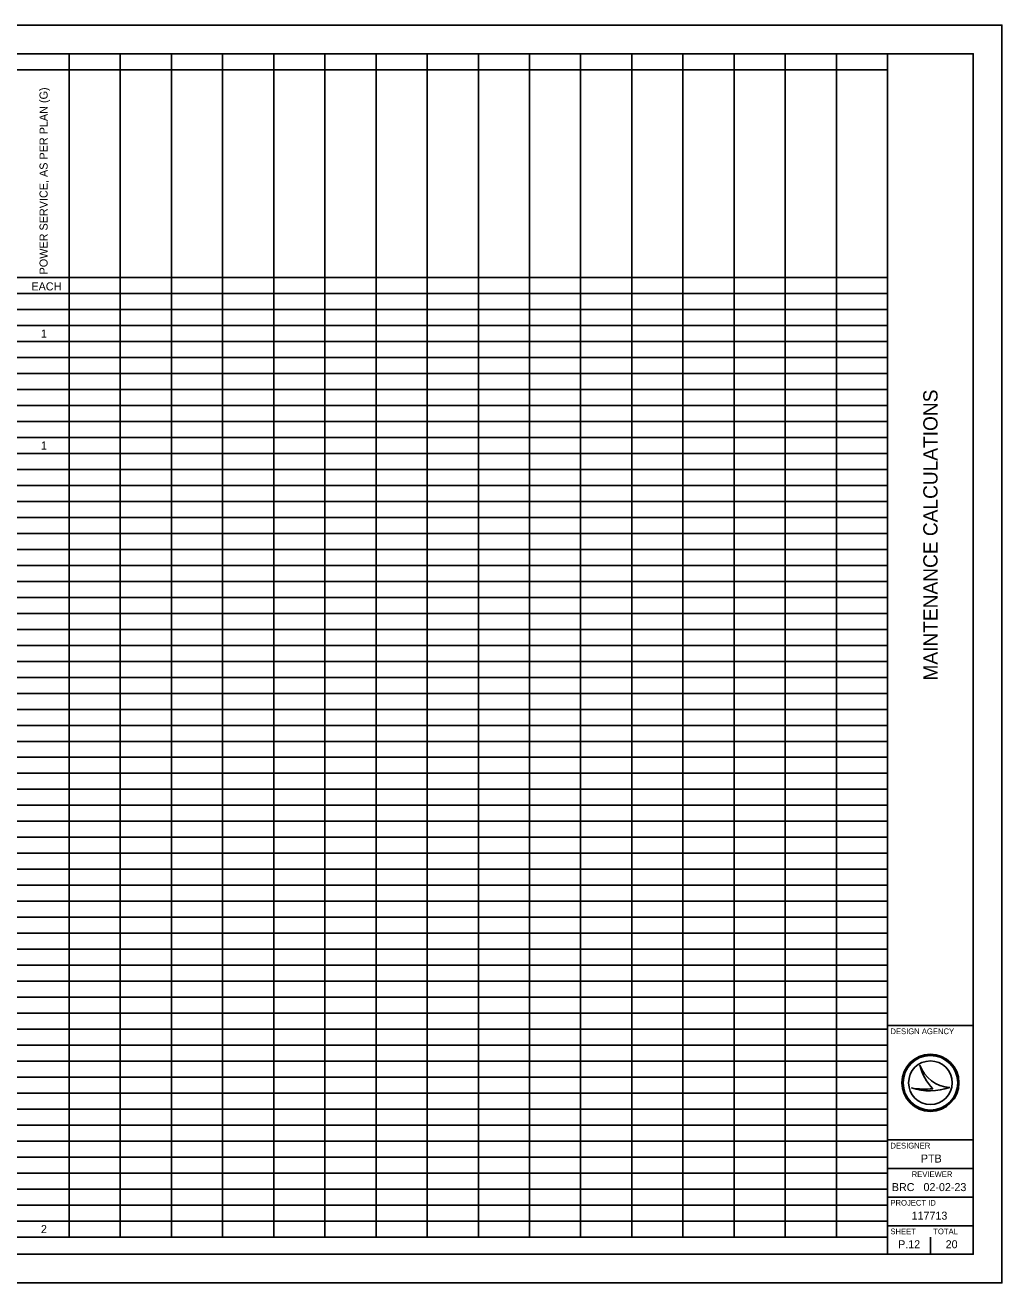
# Model space of a CAD drawing. Extents: x 0 to 34, y 0 to 22.
# Drawn here: x 16.91 to 34, y 0 to 22 of the extents above; entities that cross this region are included whole.
import ezdxf

# ---------------------------------------------------------------- set-up
doc = ezdxf.new("R2010")
doc.units = 0
for name, color, linetype in [('Default', 7, 'Continuous'), ('SH_Border', 7, 'Continuous'), ('SH_Cut_Line', 7, 'Continuous'), ('SH_Data', 7, 'Continuous')]:
    doc.layers.add(name, color=color, linetype=linetype)

msp = doc.modelspace()

# ---------------------------------------------------------------- linework, layer by layer
at = {"layer": 'Default'}
for p, q in [((7.833, 21.5), (21.259, 21.5)), ((17.679, 21.5), (17.679, 0.801)), ((18.574, 21.5), (18.574, 0.801)), ((19.469, 21.5), (19.469, 0.801)), ((20.364, 21.5), (20.364, 0.801)), ((21.259, 21.5), (32, 21.5)), ((21.259, 21.5), (21.259, 0.801)), ((22.154, 21.5), (22.154, 0.801)), ((23.049, 21.5), (23.049, 0.801)), ((23.944, 21.5), (23.944, 0.801)), ((24.839, 21.5), (24.839, 0.801)), ((25.734, 21.5), (25.734, 0.801)), ((26.629, 21.5), (26.629, 0.801)), ((27.525, 21.5), (27.525, 0.801)), ((28.42, 21.5), (28.42, 0.801)), ((29.315, 21.5), (29.315, 0.801)), ((30.21, 21.5), (30.21, 0.801)), ((31.105, 21.5), (31.105, 0.801)), ((32, 21.5), (32, 0.801)), ((8.728, 21.22), (21.259, 21.22)), ((21.259, 21.22), (32, 21.22)), ((8.728, 17.584), (21.259, 17.584)), ((21.259, 17.584), (32, 17.584)), ((7.833, 17.304), (21.259, 17.304)), ((21.259, 17.304), (32, 17.304)), ((7.833, 17.025), (21.259, 17.025)), ((21.259, 17.025), (32, 17.025)), ((7.833, 16.745), (21.259, 16.745)), ((21.259, 16.745), (32, 16.745)), ((7.833, 16.465), (21.259, 16.465)), ((21.259, 16.465), (32, 16.465)), ((7.833, 16.185), (21.259, 16.185)), ((21.259, 16.185), (32, 16.185)), ((7.833, 15.906), (21.259, 15.906)), ((21.259, 15.906), (32, 15.906)), ((7.833, 15.626), (21.259, 15.626)), ((21.259, 15.626), (32, 15.626)), ((7.833, 15.346), (21.259, 15.346)), ((21.259, 15.346), (32, 15.346)), ((7.833, 15.067), (21.259, 15.067)), ((21.259, 15.067), (32, 15.067)), ((7.833, 14.787), (21.259, 14.787)), ((21.259, 14.787), (32, 14.787)), ((7.833, 14.507), (21.259, 14.507)), ((21.259, 14.507), (32, 14.507)), ((7.833, 14.227), (21.259, 14.227)), ((21.259, 14.227), (32, 14.227)), ((7.833, 13.948), (21.259, 13.948)), ((21.259, 13.948), (32, 13.948)), ((7.833, 13.668), (21.259, 13.668)), ((21.259, 13.668), (32, 13.668)), ((7.833, 13.388), (21.259, 13.388)), ((21.259, 13.388), (32, 13.388)), ((7.833, 13.109), (21.259, 13.109)), ((21.259, 13.109), (32, 13.109)), ((7.833, 12.829), (21.259, 12.829)), ((21.259, 12.829), (32, 12.829)), ((7.833, 12.549), (21.259, 12.549)), ((21.259, 12.549), (32, 12.549)), ((7.833, 12.269), (21.259, 12.269)), ((21.259, 12.269), (32, 12.269)), ((7.833, 11.99), (21.259, 11.99)), ((21.259, 11.99), (32, 11.99)), ((7.833, 11.71), (21.259, 11.71)), ((21.259, 11.71), (32, 11.71)), ((7.833, 11.43), (21.259, 11.43)), ((21.259, 11.43), (32, 11.43)), ((7.833, 11.151), (21.259, 11.151)), ((21.259, 11.151), (32, 11.151)), ((7.833, 10.871), (21.259, 10.871)), ((21.259, 10.871), (32, 10.871)), ((7.833, 10.591), (21.259, 10.591)), ((21.259, 10.591), (32, 10.591)), ((7.833, 10.311), (21.259, 10.311)), ((21.259, 10.311), (32, 10.311)), ((7.833, 10.032), (21.259, 10.032)), ((21.259, 10.032), (32, 10.032)), ((7.833, 9.752), (21.259, 9.752)), ((21.259, 9.752), (32, 9.752)), ((7.833, 9.472), (21.259, 9.472)), ((21.259, 9.472), (32, 9.472)), ((7.833, 9.193), (21.259, 9.193)), ((21.259, 9.193), (32, 9.193)), ((7.833, 8.913), (21.259, 8.913)), ((21.259, 8.913), (32, 8.913)), ((7.833, 8.633), (21.259, 8.633)), ((21.259, 8.633), (32, 8.633)), ((7.833, 8.353), (21.259, 8.353)), ((21.259, 8.353), (32, 8.353)), ((7.833, 8.074), (21.259, 8.074)), ((21.259, 8.074), (32, 8.074)), ((7.833, 7.794), (21.259, 7.794)), ((21.259, 7.794), (32, 7.794)), ((7.833, 7.514), (21.259, 7.514)), ((21.259, 7.514), (32, 7.514)), ((7.833, 7.235), (21.259, 7.235)), ((21.259, 7.235), (32, 7.235)), ((7.833, 6.955), (21.259, 6.955)), ((21.259, 6.955), (32, 6.955)), ((7.833, 6.675), (21.259, 6.675)), ((21.259, 6.675), (32, 6.675)), ((7.833, 6.395), (21.259, 6.395)), ((21.259, 6.395), (32, 6.395)), ((7.833, 6.116), (21.259, 6.116)), ((21.259, 6.116), (32, 6.116)), ((7.833, 5.836), (21.259, 5.836)), ((21.259, 5.836), (32, 5.836)), ((7.833, 5.556), (21.259, 5.556)), ((21.259, 5.556), (32, 5.556)), ((7.833, 5.277), (21.259, 5.277)), ((21.259, 5.277), (32, 5.277)), ((7.833, 4.997), (21.259, 4.997)), ((21.259, 4.997), (32, 4.997)), ((7.833, 4.717), (21.259, 4.717)), ((21.259, 4.717), (32, 4.717)), ((7.833, 4.437), (21.259, 4.437)), ((21.259, 4.437), (32, 4.437)), ((7.833, 4.158), (21.259, 4.158)), ((21.259, 4.158), (32, 4.158)), ((7.833, 3.878), (21.259, 3.878)), ((21.259, 3.878), (32, 3.878)), ((7.833, 3.598), (21.259, 3.598)), ((21.259, 3.598), (32, 3.598)), ((7.833, 3.319), (21.259, 3.319)), ((21.259, 3.319), (32, 3.319)), ((7.833, 3.039), (21.259, 3.039)), ((21.259, 3.039), (32, 3.039)), ((7.833, 2.759), (21.259, 2.759)), ((21.259, 2.759), (32, 2.759)), ((7.833, 2.479), (21.259, 2.479)), ((21.259, 2.479), (32, 2.479)), ((7.833, 2.2), (21.259, 2.2)), ((21.259, 2.2), (32, 2.2)), ((7.833, 1.92), (21.259, 1.92)), ((21.259, 1.92), (32, 1.92)), ((7.833, 1.64), (21.259, 1.64)), ((21.259, 1.64), (32, 1.64)), ((7.833, 1.361), (21.259, 1.361)), ((21.259, 1.361), (32, 1.361)), ((7.833, 1.081), (21.259, 1.081)), ((21.259, 1.081), (32, 1.081)), ((7.833, 0.801), (21.259, 0.801)), ((21.259, 0.801), (32, 0.801))]:
    msp.add_line(p, q, dxfattribs=at)
at = {"layer": 'SH_Border'}
for p, q in [((32, 0.5), (32, 21.5)), ((32, 4.5), (33.5, 4.5)), ((32, 2.5), (33.5, 2.5)), ((32, 2), (33.5, 2)), ((32, 1.5), (33.5, 1.5)), ((32, 1), (33.5, 1))]:
    msp.add_line(p, q, dxfattribs=at)
msp.add_lwpolyline([(1.5, 21.5), (33.5, 21.5), (33.5, 0.5), (1.5, 0.5)], close=True, dxfattribs=at)
at = {"layer": 'SH_Cut_Line'}
msp.add_lwpolyline([(0, 0), (34, 0), (34, 22), (0, 22)], close=True, dxfattribs=at)
at = {"layer": 'SH_Data'}
for p, q in [((32.567, 3.81), (32.567, 3.81)), ((32.417, 3.41), (32.417, 3.41)), ((32.75, 3.5), (32.75, 3.5)), ((33.087, 3.419), (33.087, 3.419)), ((32.375, 0.675), (32.375, 0.675)), ((32.75, 0.5), (32.75, 0.8))]:
    msp.add_line(p, q, dxfattribs=at)
for radius in [0.5, 0.477, 0.477, 0.382]:
    msp.add_circle((32.75, 3.5), radius, dxfattribs=at)
for centre, radius, start, end in [((33.116, 3.998), 0.58, 198.9257, 198.9319), ((33.347, 3.97), 0.796, 191.6379, 191.6421), ((33.116, 3.998), 0.58, 198.9319, 267.1657), ((33.347, 3.97), 0.796, 191.6421, 226.0947), ((32.739, 4.37), 1.013, 251.4576, 290.0832), ((32.648, 4.654), 1.266, 259.4964, 259.4995), ((32.739, 4.37), 1.013, 251.4527, 251.4576), ((32.648, 4.654), 1.266, 259.4995, 276.6672)]:
    msp.add_arc(centre, radius, start, end, dxfattribs=at)

# ---------------------------------------------------------------- texts
at = {"layer": 'Default'}
msp.add_text('POWER SERVICE, AS PER PLAN (G)', height=0.14154, rotation=90, dxfattribs=at).set_placement((17.302, 17.64))
for s, height, p in [('EACH', 0.1415, (17.018, 17.36)), ('1', 0.142, (17.186, 16.534)), ('1', 0.142, (17.186, 14.576)), ('2', 0.142, (17.184, 0.87))]:
    msp.add_text(s, height=height, dxfattribs=at).set_placement(p)
at = {"layer": 'SH_Data'}
msp.add_text('MAINTENANCE CALCULATIONS', height=0.25, rotation=90, dxfattribs=at).set_placement((32.875, 10.536))
for s, height, p in [('DESIGN AGENCY', 0.1, (32.05, 4.35)), ('DESIGNER', 0.1, (32.05, 2.35)), ('PTB', 0.14, (32.584, 2.105)), ('REVIEWER', 0.1, (32.422, 1.85)), ('BRC', 0.14, (32.075, 1.605)), ('02-02-23', 0.14, (32.629, 1.605)), ('PROJECT ID', 0.1, (32.05, 1.35)), ('117713', 0.14, (32.421, 1.105)), ('SHEET', 0.1, (32.05, 0.85)), ('TOTAL', 0.1, (32.8, 0.85)), ('P.12', 0.14, (32.185, 0.605)), ('20', 0.14, (33.017, 0.605))]:
    msp.add_text(s, height=height, dxfattribs=at).set_placement(p)

doc.saveas('drawing.dxf')
